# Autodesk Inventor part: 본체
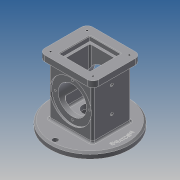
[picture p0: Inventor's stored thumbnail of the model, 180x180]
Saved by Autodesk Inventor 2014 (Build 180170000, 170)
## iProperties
Created: 2019-08
Part Number: 본체
Material: Generic
Document SubType Name: Modeling
Designer: kb542-18
Density: 1 g/cm^3
Appearance: Default
Author: kb542-18
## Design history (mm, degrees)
sketch "스케치1"
  geometry: C1 r 67.5 at (0, 0); 1 further point
  constraints: 1 centre point, 1 coincident
  dimensions: "d0" = 135 diameter of C1
extrude "돌출1" new body sketch "스케치1" distance "d1" = 10; taper "d2" = 0 deg
sketch "스케치2"
  geometry: C1 r 67.5 at (0, 0) reference; 3 further points
  constraints: 2 vertical alignment, 1 horizontal alignment
  dimensions: "d3" = 59 distance of C1.centre point (0, 59); "d4" = 59 distance of point (-59, 0) C1.centre; "d5" = 59 distance of point (0, -59) C1.centre
hole "구멍1" sketch "스케치2" at (0, 59), (-59, 0), (0, -59) diameter "d6" = 9; stored, may be unused: countersink angle "d10" = 90 deg, drill point angle "d12" = 118 deg; dims "d7" = 6, "d8" = 4, "d9" = 2, "d11" = 8
sketch "스케치3"
  geometry: L1 (37, -33)-(-37, -33); L2 (-37, -33)-(-37, 33); L3 (-37, 33)-(37, 33); L4 (37, 33)-(37, -33); L5 (37, -33)-(-37, 33); L6 (-37, -33)-(37, 33); C1 r 67.5 at (0, 0) reference
  constraints: 12 end point, 2 midpoint, 2 parallel, 1 horizontal, 1 perpendicular
  dimensions: "d13" = 74 distance of L2.end L3.end; "d14" = 66 distance of L1.end L2.end
extrude "돌출2" join sketch "스케치3" distance "d15" = 98; taper "d16" = 0 deg
sketch "스케치4"
  geometry: L1 (46, -41)-(-46, -41); L2 (-46, -41)-(-46, 41); L3 (-46, 41)-(46, 41); L4 (46, 41)-(46, -41); L5 (46, -41)-(-46, 41); L6 (-46, -41)-(46, 41); 1 further point
  constraints: 12 end point, 2 midpoint, 2 parallel, 1 horizontal, 1 perpendicular
  dimensions: "d17" = 92 distance of L2.end L3.end; "d18" = 82 distance of L3.end L1.start
extrude "돌출3" join sketch "스케치4" distance "d19" = 10; taper "d20" = 0 deg
chamfer "모따기1" distance "d21" = 3; stored, may be unused: second distance "d22" = 2, angle "d23" = 45 deg
fillet "모깎기1" dims "d35" = 10
sketch "스케치6"
  geometry: C1 r 12.5 at (0, 0); 1 further point
  constraints: 1 centre point, 1 coincident
  dimensions: "d36" = 25 diameter of C1
extrude "돌출4" cut sketch "스케치6" stored distance "d37" = 10; taper "d38" = 0 deg
sketch "스케치7"
  geometry: C1 r 12.5 at (0, 0) reference; C2 r 67.5 at (0, 0) reference; C3 r 25 at (0, 0)
  constraints: 1 centre point, 1 coincident
  dimensions: "d39" = 50 diameter of C3
extrude "돌출5" cut sketch "스케치7" distance "d40" = 18; taper "d41" = 0 deg
sketch "스케치10"
  geometry: L1 (95.883, -3)-(95.883, -10) reference; L2 (95.883, -10)-(-21.883, -10) reference; L3 (-21.883, -10)-(-21.883, -3) reference; L4 (-18.419, 0)-(0, 0) reference; L5 (0, 0)-(74, 0) reference; L6 (74, 0)-(92.419, 0) reference; L7 (0, 0)-(0, 88) reference; L8 (-8.798, 88)-(-8.798, 98) reference; L9 (82.798, 98)-(82.798, 88) reference; L10 (74, 88)-(74, 0) reference; L11 (0, 88)-(-8.798, 88) reference; L12 (-8.798, 98)-(82.798, 98) reference; L13 (82.798, 88)-(74, 88) reference; L14 (74, 88)-(0, 88) reference; C1 r 35 at (37, 44); 2 further points
  constraints: 1 centre point, 1 midpoint, 1 vertical alignment, 2 other
  dimensions: "d50" = 70 diameter of C1; "d52" = 54 distance from line of C1.centre L2
extrude "돌출8" cut sketch "스케치10" distance "d53" = 3; taper "d54" = 0 deg
sketch "스케치11"
  geometry: C1 r 35 at (0, 0) reference; C2 r 24 at (0, 0); 1 further point
  constraints: 1 centre point, 1 coincident
  dimensions: "d55" = 48 diameter of C2
extrude "돌출9" cut sketch "스케치11" stored distance "d56" = 3; taper "d57" = 0 deg
sketch "스케치12"
  geometry: C1 r 24 at (0, 0) reference; 2 further points
  constraints: 1 vertical alignment
  dimensions: "d58" = 29 distance of C1.centre point (0, 29)
hole "구멍3" sketch "스케치12" at (0, 29) diameter "d59" = 3.242; stored, may be unused: countersink angle "d63" = 90 deg, drill point angle "d65" = 118 deg; dims "d60" = 4, "d61" = 4, "d62" = 2, "d64" = 6
sketch "스케치14"
  geometry: C1 r 64.5 at (0, 0) reference; C2 r 59 at (0, 0)
  constraints: 1 centre point, 1 coincident, 1 other
  dimensions: "d92" = 118 diameter of C2
feature "엠보싱1" sketch "스케치14" dims "d93" = 0.5, "d94" = 0
fillet "모깎기2" dims "d95" = 3
fillet "모깎기3" dims "d96" = 3
fillet "모깎기4" dims "d97" = 3
sketch "스케치15"
  geometry: L1 (26, -26)-(-26, -26); L2 (-26, -26)-(-26, 26); L3 (-26, 26)-(26, 26); L4 (26, 26)-(26, -26); L5 (26, -26)-(-26, 26); L6 (-26, -26)-(26, 26); C1 r 12.5 at (0, 0) reference
  constraints: 12 end point, 2 midpoint, 2 parallel, 1 horizontal, 1 perpendicular
  dimensions: "d103" = 52 distance of L2.end L3.end; "d104" = 52 distance of L3.end L1.start
extrude "돌출10" cut sketch "스케치15" distance "d105" = 8; taper "d106" = 0 deg
sketch "스케치16"
  geometry: L1 (22, -22)-(-22, -22); L2 (-22, -22)-(-22, 22); L3 (-22, 22)-(22, 22); L4 (22, 22)-(22, -22); L5 (22, -22)-(-22, 22); L6 (-22, -22)-(22, 22); C1 r 12.5 at (0, 0) reference
  constraints: 12 end point, 2 midpoint, 2 parallel, 1 horizontal, 1 perpendicular
  dimensions: "d107" = 44 distance of L2.end L3.end; "d108" = 44 distance of L1.end L2.end
extrude "돌출11" cut sketch "스케치16" distance "d109" = 74; taper "d110" = 0 deg
sketch "스케치17"
  geometry: A1 r 10 centre (36, -31) between (36, -41) and (46, -31) reference; A2 r 10 centre (36, 31) between (46, 31) and (36, 41) reference; A3 r 10 centre (-36, 31) between (-36, 41) and (-46, 31) reference; A4 r 10 centre (-36, -31) between (-46, -31) and (-36, -41) reference; 5 further points
  constraints: 4 coincident
hole "구멍7" sketch "스케치17" at (-36, 31), (36, 31), (-36, -31), (36, -31) diameter "d111" = 3.242; stored, may be unused: countersink angle "d115" = 90 deg, drill point angle "d117" = 118 deg; dims "d112" = 4, "d113" = 4, "d114" = 2, "d116" = 6
sketch "스케치18"
  geometry: L1 (0, -11.226)-(-10, -11.226) reference; L2 (-10, -11.226)-(-10, -2.552) reference; L3 (0, -0.276)-(0, -11.226) reference; L4 (0, 70.674)-(0, 59.724) reference; L5 (-10, 62)-(-10, 70.674) reference; L6 (-10, 70.674)-(0, 70.674) reference; L7 (85, -0.276)-(0, -0.276) reference; L8 (85, -0.276)-(85, 59.724) reference; L9 (88, 64.92)-(88, 82.556) reference; L10 (91, 86.18)-(98, 86.18) reference; L11 (98, 86.18)-(98, -26.732) reference; L12 (98, -26.732)-(91, -26.732) reference; L13 (88, -23.108)-(88, -5.472) reference; L14 (85, 59.724)-(0, 59.724) reference; L15 (-10, 0)-(-10, 59.448) reference; L16 (-10, -2.552)-(-4, -2.552) reference; L17 (-4, 0)-(-10, 0) reference; L18 (-10, 59.448)-(-4, 59.448) reference; L19 (-4, 62)-(-10, 62) reference; L20 (0, 59.724)-(0, -0.276) reference; 4 further points
  constraints: 2 horizontal alignment, 2 vertical alignment, 1 midpoint, 4 other
  dimensions: "d118" = 37 distance from line of point (61, 29.724) L11; "d119" = 43 distance of point (18, 29.724) point (61, 29.724)
  node "절단 모서리 투영3"
hole "구멍8" sketch "스케치18" diameter "d120" = 4.917; stored, may be unused: countersink angle "d124" = 90 deg, drill point angle "d126" = 118 deg; dims "d121" = 4, "d122" = 4, "d123" = 2, "d125" = 6
hole "구멍9" sketch "스케치18" diameter "d127" = 4.917; stored, may be unused: countersink angle "d131" = 90 deg, drill point angle "d133" = 118 deg; dims "d128" = 4, "d129" = 4, "d130" = 2, "d132" = 6
fillet "모깎기7" dims "d134" = 3
chamfer "모따기3" distance "d135" = 1; stored, may be unused: second distance "d136" = 2, angle "d137" = 45 deg
fillet "모깎기8" dims "d138" = 3
fillet "모깎기9" dims "d139" = 3
node "솔리드1"
mirror "대칭1"
pattern_circular "원형 패턴1" dims angle "d67" = 360 deg
mirror "대칭2"
sketch "스케치13"
  geometry: L1 (3, 89.456)-(10, 89.456) reference; L2 (10, 89.456)-(10, -23.456) reference; L3 (10, -23.456)-(3, -23.456) reference; L4 (0, -19.832)-(0, 0) reference; L5 (0, 0)-(0, 66) reference; L6 (0, 66)-(0, 85.832) reference; L7 (0, 0)-(-88, 0) reference; L8 (-88, -7.95)-(-98, -7.95) reference; L9 (-98, 73.95)-(-88, 73.95) reference; L10 (-88, 66)-(0, 66) reference; L11 (-88, 73.95)-(-88, 66) reference; L12 (-98, -7.95)-(-98, 73.95) reference; L13 (-88, 0)-(-88, -7.95) reference; L14 (-88, 66)-(-88, 0) reference; 3 further points
  constraints: 1 horizontal alignment, 1 midpoint, 2 other
node "절단 모서리 투영1"
node "절단 모서리 투영2"
